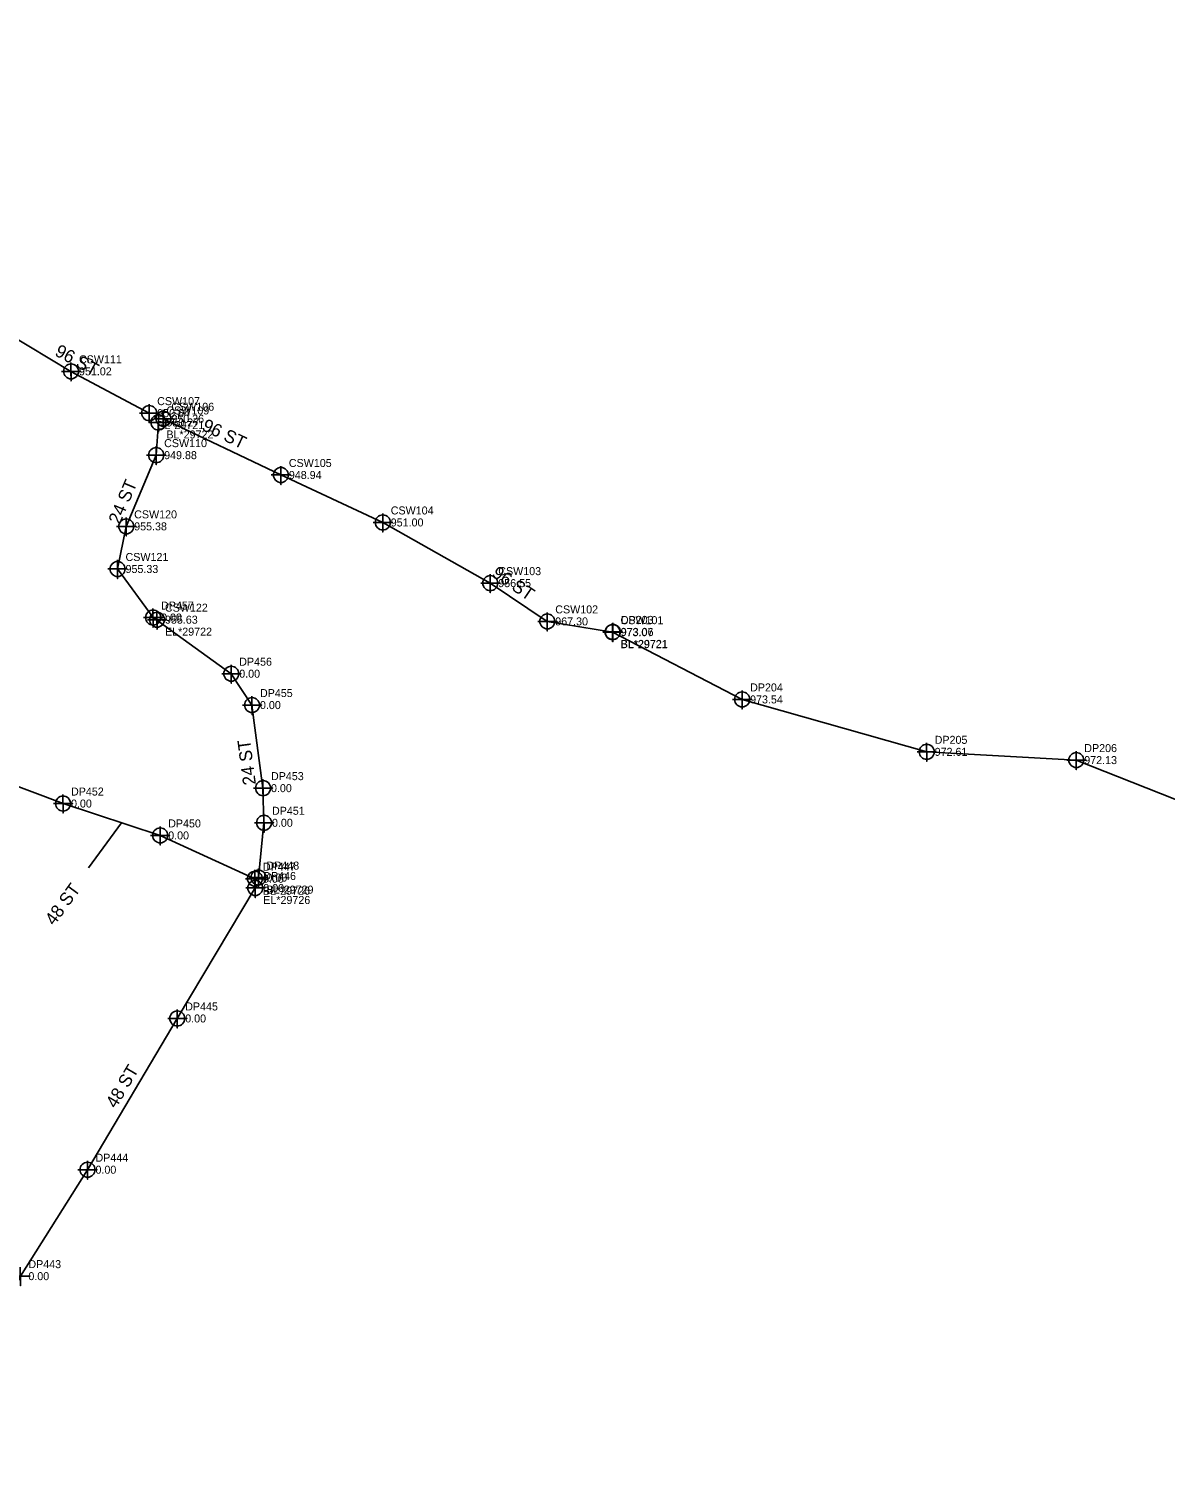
# Model space of a CAD drawing. Extents: x 1182504 to 1186036, y 573002 to 575111.
# Drawn here: x 1184140 to 1184495, y 573535.6 to 573983.4 of the extents above; entities that cross this region are included whole.
import ezdxf

# ---------------------------------------------------------------- set-up
doc = ezdxf.new("R2010")
doc.units = 0
for name, color, linetype in [('Exist Utilities Telephone UG Conduit SUE LOS B', 7, 'Continuous'), ('Exist Utilities Telephone UG Conduit SUE LOS B Cogo Comment', 7, 'Continuous'), ('Exist Utilities Telephone UG Conduit SUE LOS B Cogo Elevation', 7, 'Continuous'), ('Exist Utilities Telephone UG Conduit SUE LOS B Cogo Number', 7, 'Continuous'), ('Exist Utilities Telephone UG Conduit SUE LOS B Cogo Point CELL', 7, 'Continuous'), ('Exist Utilities Telephone UG Conduit SUE LOS B Leader', 7, 'Continuous'), ('Exist Utilities Telephone UG Conduit SUE LOS B Text', 7, 'Continuous')]:
    doc.layers.add(name, color=color, linetype=linetype)

msp = doc.modelspace()

# ---------------------------------------------------------------- linework, layer by layer
at = {"layer": 'Exist Utilities Telephone UG Conduit SUE LOS B'}
for points in [[(1183461.9, 574217.61), (1183507.97, 574205.1), (1183555.78, 574190.97), (1183600.29, 574174.7), (1183642.38, 574158.78), (1183685.83, 574141.54), (1183729.44, 574124.53), (1183772.61, 574105.48), (1183815.48, 574084.72), (1183856.9, 574064.89), (1183910.26, 574040.72), (1183938.65, 574025.64), (1184017.13, 573974.93), (1184056.25, 573949.51), (1184095.95, 573918.75), (1184120.25, 573896.12), (1184153.18, 573876.37), (1184177.6, 573863.32)], [(1184210.63, 573717.89), (1184181.04, 573731.42), (1184150.69, 573741.38), (1184111.86, 573755.94), (1184075.03, 573792.9), (1184045.3, 573827.54), (1184014.43, 573862.52), (1183980.03, 573902.29), (1183947.95, 573939.47), (1183913, 573967.93)], [(1184182.02, 573861.57), (1184218.73, 573844), (1184250.56, 573829.18), (1184284.14, 573810.22), (1184301.94, 573798.27), (1184322.33, 573794.9)], [(1184180.49, 573860.41), (1184179.78, 573850.2), (1184170.42, 573827.95), (1184167.72, 573814.64), (1184178.81, 573799.47)], [(1184211.74, 573718.25), (1184213.46, 573735.37), (1184213.15, 573746.19), (1184209.71, 573772.14), (1184203.23, 573781.93), (1184178.81, 573799.47)], [(1184322.33, 573794.9), (1184362.8, 573773.9), (1184420.45, 573757.53), (1184467.17, 573754.95), (1184515.32, 573735.91)], [(1184020.78, 573306.4), (1183988.14, 573330.66), (1183985.98, 573336.24), (1183991.53, 573344.95), (1184017.37, 573382.34), (1184043.22, 573419.6), (1184071.03, 573458.88), (1184092.18, 573492.71), (1184101.38, 573521.29), (1184118.41, 573555.81), (1184137.37, 573593.76), (1184158.33, 573627.01), (1184186.36, 573674.25), (1184210.73, 573715)]]:
    msp.add_lwpolyline(points, dxfattribs=at)
at = {"layer": 'Exist Utilities Telephone UG Conduit SUE LOS B Cogo Point CELL'}
for points in [[(1184153.17, 573879.19), (1184153.2, 573873.37), (1184153.18, 573876.37), (1184156.2, 573876.37), (1184150.2, 573876.37)], [(1184177.58, 573866.14), (1184177.62, 573860.32), (1184177.6, 573863.32), (1184180.62, 573863.32), (1184174.62, 573863.32)], [(1184180.47, 573863.22), (1184180.5, 573857.41), (1184180.49, 573860.41), (1184183.5, 573860.41), (1184177.5, 573860.41)], [(1184182, 573864.38), (1184182.04, 573858.57), (1184182.02, 573861.57), (1184185.04, 573861.57), (1184179.04, 573861.57)], [(1184179.76, 573853.02), (1184179.8, 573847.2), (1184179.78, 573850.2), (1184182.8, 573850.2), (1184176.8, 573850.2)], [(1184218.72, 573846.81), (1184218.75, 573841), (1184218.73, 573844), (1184221.75, 573844), (1184215.75, 573844)], [(1184170.4, 573830.77), (1184170.44, 573824.95), (1184170.42, 573827.95), (1184173.44, 573827.95), (1184167.44, 573827.95)], [(1184250.55, 573831.99), (1184250.58, 573826.18), (1184250.56, 573829.18), (1184253.58, 573829.18), (1184247.58, 573829.18)], [(1184167.7, 573817.46), (1184167.73, 573811.64), (1184167.72, 573814.64), (1184170.73, 573814.64), (1184164.73, 573814.64)], [(1184284.12, 573813.04), (1184284.16, 573807.22), (1184284.14, 573810.22), (1184287.16, 573810.22), (1184281.16, 573810.22)], [(1184178.79, 573802.29), (1184178.83, 573796.47), (1184178.81, 573799.47), (1184181.83, 573799.47), (1184175.83, 573799.47)], [(1184180.02, 573801.63), (1184180.06, 573795.81), (1184180.04, 573798.81), (1184183.06, 573798.81), (1184177.06, 573798.81)], [(1184301.92, 573801.08), (1184301.96, 573795.27), (1184301.94, 573798.27), (1184304.96, 573798.27), (1184298.96, 573798.27)], [(1184322.32, 573797.71), (1184322.35, 573791.9), (1184322.33, 573794.9), (1184325.35, 573794.9), (1184319.35, 573794.9)], [(1184322.4, 573797.8), (1184322.43, 573791.99), (1184322.42, 573794.99), (1184325.43, 573794.99), (1184319.43, 573794.99)], [(1184203.22, 573784.75), (1184203.25, 573778.93), (1184203.23, 573781.93), (1184206.25, 573781.93), (1184200.25, 573781.93)], [(1184362.79, 573776.71), (1184362.82, 573770.9), (1184362.8, 573773.9), (1184365.82, 573773.9), (1184359.82, 573773.9)], [(1184209.69, 573774.95), (1184209.73, 573769.14), (1184209.71, 573772.14), (1184212.73, 573772.14), (1184206.73, 573772.14)], [(1184420.43, 573760.34), (1184420.46, 573754.53), (1184420.45, 573757.53), (1184423.46, 573757.53), (1184417.46, 573757.53)], [(1184467.16, 573757.77), (1184467.19, 573751.95), (1184467.17, 573754.95), (1184470.19, 573754.95), (1184464.19, 573754.95)], [(1184213.14, 573749), (1184213.17, 573743.19), (1184213.15, 573746.19), (1184216.17, 573746.19), (1184210.17, 573746.19)], [(1184150.67, 573744.19), (1184150.7, 573738.38), (1184150.69, 573741.38), (1184153.7, 573741.38), (1184147.7, 573741.38)], [(1184213.45, 573738.19), (1184213.48, 573732.37), (1184213.46, 573735.37), (1184216.48, 573735.37), (1184210.48, 573735.37)], [(1184181.02, 573734.23), (1184181.05, 573728.42), (1184181.04, 573731.42), (1184184.05, 573731.42), (1184178.05, 573731.42)], [(1184210.61, 573720.71), (1184210.64, 573714.89), (1184210.63, 573717.89), (1184213.64, 573717.89), (1184207.64, 573717.89)], [(1184211.72, 573721.06), (1184211.76, 573715.25), (1184211.74, 573718.25), (1184214.76, 573718.25), (1184208.76, 573718.25)], [(1184210.72, 573717.82), (1184210.75, 573712), (1184210.73, 573715), (1184213.75, 573715), (1184207.75, 573715)], [(1184186.34, 573677.07), (1184186.38, 573671.25), (1184186.36, 573674.25), (1184189.38, 573674.25), (1184183.38, 573674.25)], [(1184158.32, 573629.82), (1184158.35, 573624.01), (1184158.33, 573627.01), (1184161.35, 573627.01), (1184155.35, 573627.01)], [(1184137.36, 573596.57), (1184137.39, 573590.76), (1184137.37, 573593.76), (1184140.39, 573593.76), (1184134.39, 573593.76)]]:
    msp.add_lwpolyline(points, dxfattribs=at)
for centre in [(1184153.2, 573876.37), (1184177.62, 573863.32), (1184180.5, 573860.41), (1184182.04, 573861.57), (1184179.8, 573850.2), (1184218.75, 573844), (1184170.44, 573827.95), (1184250.58, 573829.18), (1184167.73, 573814.64), (1184284.16, 573810.22), (1184178.83, 573799.47), (1184180.06, 573798.81), (1184301.96, 573798.27), (1184322.35, 573794.9), (1184322.43, 573794.99), (1184203.25, 573781.93), (1184209.73, 573772.14), (1184362.82, 573773.9), (1184420.46, 573757.53), (1184467.19, 573754.95), (1184213.17, 573746.19), (1184150.7, 573741.38), (1184213.48, 573735.37), (1184181.05, 573731.42), (1184210.64, 573717.89), (1184211.76, 573718.25), (1184210.75, 573715), (1184186.38, 573674.25), (1184158.35, 573627.01)]:
    msp.add_circle(centre, 2.34, dxfattribs=at)
at = {"layer": 'Exist Utilities Telephone UG Conduit SUE LOS B Leader'}
msp.add_line((1184168.93, 573735.39), (1184158.7, 573721.34), dxfattribs=at)

# ---------------------------------------------------------------- texts
at = {"layer": 'Exist Utilities Telephone UG Conduit SUE LOS B Cogo Comment'}
for s, p in [('BL*29721', (1184180.1, 573858.32)), ('BL*29722', (1184182.99, 573855.41)), ('EL*29722', (1184182.54, 573793.81)), ('BL*29721', (1184324.83, 573789.9)), ('BL*29721', (1184324.92, 573789.99)), ('BL*29726', (1184213.13, 573712.89)), ('BL*29729', (1184214.24, 573713.25)), ('EL*29726', (1184213.23, 573710))]:
    msp.add_text(s, height=2.5, dxfattribs=at).set_placement(p)
at = {"layer": 'Exist Utilities Telephone UG Conduit SUE LOS B Cogo Elevation'}
for s, p in [('951.02', (1184155.68, 573875.12)), ('950.64', (1184180.1, 573862.07)), ('950.27', (1184182.99, 573859.16)), ('950.26', (1184184.52, 573860.32)), ('949.88', (1184182.28, 573848.95)), ('948.94', (1184221.23, 573842.75)), ('951.00', (1184253.06, 573827.93)), ('955.38', (1184172.92, 573826.7)), ('955.33', (1184170.22, 573813.39)), ('956.55', (1184286.64, 573808.97)), ('0.00', (1184181.31, 573798.22)), ('955.63', (1184182.54, 573797.56)), ('967.30', (1184304.44, 573797.02)), ('973.07', (1184324.83, 573793.65)), ('973.06', (1184324.92, 573793.74)), ('0.00', (1184205.73, 573780.68)), ('0.00', (1184212.21, 573770.89)), ('973.54', (1184365.3, 573772.65)), ('972.61', (1184422.95, 573756.28)), ('972.13', (1184469.67, 573753.7)), ('0.00', (1184215.65, 573744.94)), ('0.00', (1184153.19, 573740.13)), ('0.00', (1184215.96, 573734.12)), ('0.00', (1184183.54, 573730.17)), ('0.00', (1184213.13, 573716.64)), ('0.00', (1184214.24, 573717)), ('0.00', (1184213.23, 573713.75)), ('0.00', (1184188.86, 573673)), ('0.00', (1184160.83, 573625.76)), ('0.00', (1184139.87, 573592.51))]:
    msp.add_text(s, height=2.5, dxfattribs=at).set_placement(p)
at = {"layer": 'Exist Utilities Telephone UG Conduit SUE LOS B Cogo Number'}
for s, p in [('CSW111', (1184155.68, 573878.87)), ('CSW107', (1184180.1, 573865.82)), ('CSW106', (1184184.52, 573864.07)), ('CSW109', (1184182.99, 573862.91)), ('CSW110', (1184182.28, 573852.7)), ('CSW105', (1184221.23, 573846.5)), ('CSW120', (1184172.92, 573830.45)), ('CSW104', (1184253.06, 573831.68)), ('CSW121', (1184170.22, 573817.14)), ('CSW103', (1184286.64, 573812.72)), ('DP457', (1184181.31, 573801.97)), ('CSW122', (1184182.54, 573801.31)), ('CSW102', (1184304.44, 573800.77)), ('CSW101', (1184324.83, 573797.4)), ('DP203', (1184324.92, 573797.49)), ('DP456', (1184205.73, 573784.43)), ('DP455', (1184212.21, 573774.64)), ('DP204', (1184365.3, 573776.4)), ('DP205', (1184422.95, 573760.03)), ('DP206', (1184469.67, 573757.45)), ('DP453', (1184215.65, 573748.69)), ('DP452', (1184153.19, 573743.88)), ('DP450', (1184183.54, 573733.92)), ('DP451', (1184215.96, 573737.87)), ('DP447', (1184213.13, 573720.39)), ('DP448', (1184214.24, 573720.75)), ('DP446', (1184213.23, 573717.5)), ('DP445', (1184188.86, 573676.75)), ('DP444', (1184160.83, 573629.51)), ('DP443', (1184139.87, 573596.26))]:
    msp.add_text(s, height=2.5, dxfattribs=at).set_placement(p)
at = {"layer": 'Exist Utilities Telephone UG Conduit SUE LOS B Text'}
for s, rotation, p in [('96 ST', 331.8703, (1184147.83, 573881.5)), ('96 ST', 334.4242, (1184193.81, 573858.14)), ('24 ST', 67.1859, (1184168.4, 573828.3)), ('96 ST', 326.1199, (1184284.34, 573812.5)), ('24 ST', 97.5526, (1184210.97, 573747.4)), ('48 ST', 53.9157, (1184147.94, 573703.03)), ('48 ST', 59.3238, (1184167.22, 573645.92))]:
    msp.add_text(s, height=4, rotation=rotation, dxfattribs=at).set_placement(p)

doc.saveas('drawing.dxf')
